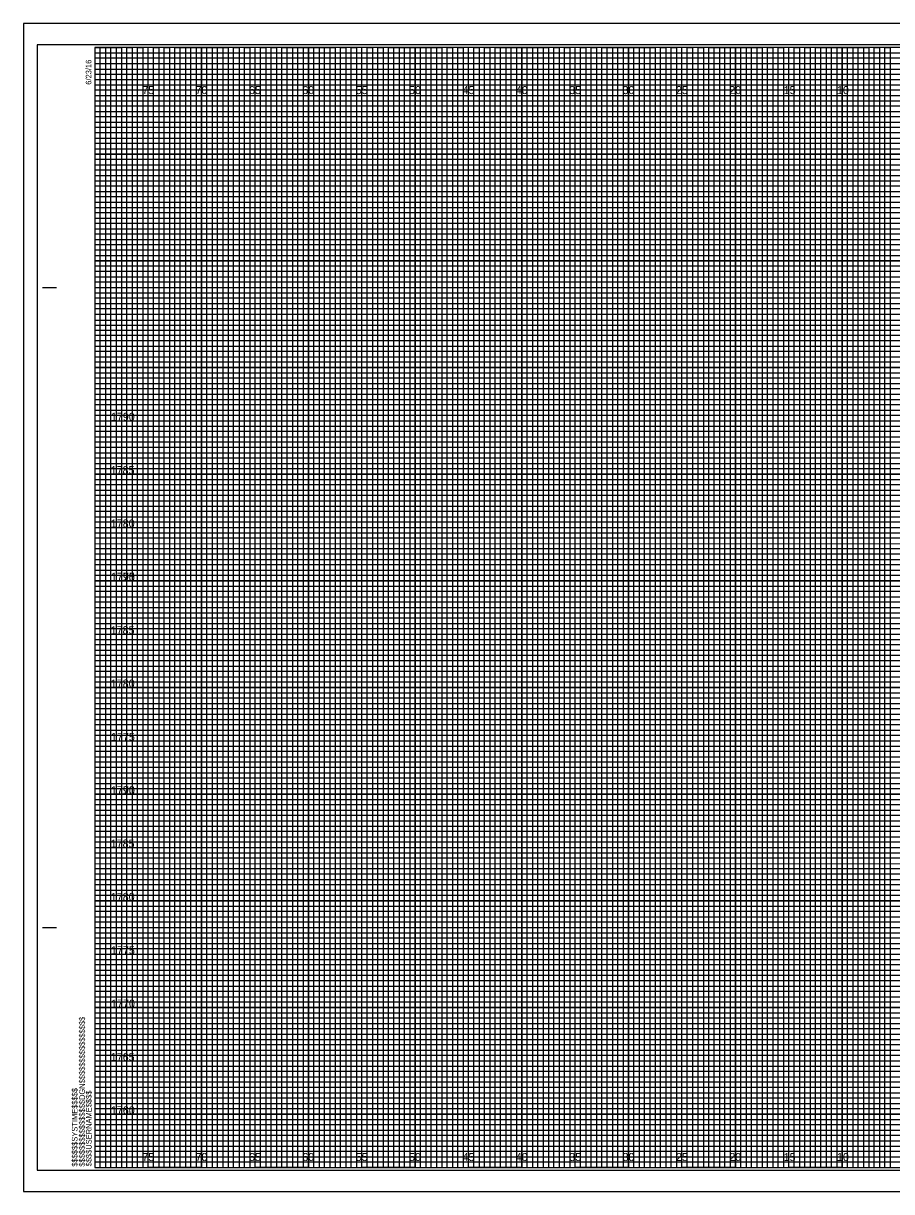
# Model space of a CAD drawing. Extents: x -7 to 162, y -2 to 217.
# Drawn here: x -6.7 to 74.6, y 107.7 to 217.2 of the extents above; entities that cross this region are included whole.
import ezdxf

# ---------------------------------------------------------------- set-up
doc = ezdxf.new("R2010")
doc.units = 0
for name, color, linetype in [('Raster_Level_0', 7, 'Continuous'), ('Scratch_Level_3', 7, 'Continuous'), ('Sheet Cross Section CELL', 7, 'Continuous'), ('Sheet Cross Section Grid Major CELL', 7, 'Continuous'), ('Sheet Cross Section Grid Middle CELL', 7, 'Continuous'), ('Sheet Cross Section Grid Minor 1 CELL', 7, 'Continuous'), ('Sheet Cross Section Grid Minor 2 CELL', 7, 'Continuous'), ('Sheet Cutting Line CELL', 7, 'Continuous'), ('Sheet DOT Grid CELL', 7, 'Continuous'), ('Sheet Plot Border Inside CELL', 7, 'Continuous'), ('Sheet Plot Border Outside CELL', 7, 'Continuous')]:
    doc.layers.add(name, color=color, linetype=linetype)

msp = doc.modelspace()

# ---------------------------------------------------------------- linework, layer by layer
at = {"layer": 'Sheet Cross Section CELL'}
for p, q in [((-4.9, 192.5), (-3.65, 192.5)), ((-4.85, 192.5), (-3.6, 192.5)), ((-4.9, 132.5), (-3.65, 132.5)), ((-4.85, 132.5), (-3.6, 132.5)), ((0, 110), (0, 110)), ((0, 110), (0, 110)), ((0, 110), (0, 110)), ((0, 110), (0, 110)), ((0, 110), (0, 110)), ((0, 110), (0, 110)), ((0, 110), (0, 110))]:
    msp.add_line(p, q, dxfattribs=at)
msp.add_lwpolyline([(160, 215), (0, 215), (0, 110), (160, 110)], close=True, dxfattribs=at)
at = {"layer": 'Sheet Cross Section Grid Major CELL'}
for p, q in [((5, 215), (0, 215)), ((5, 110), (5, 215)), ((15, 215), (10, 215)), ((10, 215), (10, 110)), ((15, 110), (15, 215)), ((25, 215), (20, 215)), ((20, 215), (20, 110)), ((25, 110), (25, 215)), ((35, 215), (30, 215)), ((30, 215), (30, 110)), ((35, 110), (35, 215)), ((45, 215), (40, 215)), ((40, 215), (40, 110)), ((45, 110), (45, 215)), ((55, 215), (50, 215)), ((50, 215), (50, 110)), ((55, 110), (55, 215)), ((65, 215), (60, 215)), ((60, 215), (60, 110)), ((65, 110), (65, 215)), ((75, 215), (70, 215)), ((70, 215), (70, 110)), ((10, 110), (5, 110)), ((20, 110), (15, 110)), ((30, 110), (25, 110)), ((40, 110), (35, 110)), ((50, 110), (45, 110)), ((60, 110), (55, 110)), ((70, 110), (65, 110))]:
    msp.add_line(p, q, dxfattribs=at)
for points in [[(0, 210), (160, 210), (160, 205), (0, 205)], [(0, 200), (160, 200), (160, 195), (0, 195)], [(0, 190), (160, 190), (160, 185), (0, 185)], [(0, 180), (160, 180), (160, 175), (0, 175)], [(0, 170), (160, 170), (160, 165), (0, 165)], [(0, 160), (160, 160), (160, 155), (0, 155)], [(0, 150), (160, 150), (160, 145), (0, 145)], [(0, 140), (160, 140), (160, 135), (0, 135)], [(0, 130), (160, 130), (160, 125), (0, 125)], [(0, 120), (160, 120), (160, 115), (0, 115)]]:
    msp.add_lwpolyline(points, dxfattribs=at)
at = {"layer": 'Sheet Cross Section Grid Middle CELL'}
for points in [[(0, 215), (2.5, 215), (2.5, 110), (7.5, 110), (7.5, 215), (12.5, 215), (12.5, 110), (17.5, 110), (17.5, 215), (22.5, 215), (22.5, 110), (27.5, 110), (27.5, 215), (32.5, 215), (32.5, 110), (37.5, 110), (37.5, 215), (42.5, 215), (42.5, 110), (47.5, 110), (47.5, 215), (52.5, 215), (52.5, 110), (57.5, 110), (57.5, 215), (62.5, 215), (62.5, 110), (67.5, 110), (67.5, 215), (72.5, 215), (72.5, 110), (77.5, 110)], [(0, 212.5), (137.5, 212.5)], [(0, 202.5), (160, 202.5), (160, 207.5), (0, 207.5)], [(0, 192.5), (160, 192.5), (160, 197.5), (0, 197.5)], [(0, 182.5), (160, 182.5), (160, 187.5), (0, 187.5)], [(0, 172.5), (160, 172.5), (160, 177.5), (0, 177.5)], [(0, 162.5), (160, 162.5), (160, 167.5), (0, 167.5)], [(0, 152.5), (160, 152.5), (160, 157.5), (0, 157.5)], [(0, 142.5), (160, 142.5), (160, 147.5), (0, 147.5)], [(0, 132.5), (160, 132.5), (160, 137.5), (0, 137.5)], [(0, 122.5), (160, 122.5), (160, 127.5), (0, 127.5)], [(0, 112.5), (160, 112.5), (160, 117.5), (0, 117.5)]]:
    msp.add_lwpolyline(points, dxfattribs=at)
at = {"layer": 'Sheet Cross Section Grid Minor 1 CELL'}
for p, q in [((0, 214.5), (130, 214.5)), ((130, 213.99), (0, 213.99)), ((0, 213.99), (0, 213.5)), ((0, 213.5), (130, 213.5)), ((130, 212.94), (0, 212.94)), ((0, 212.94), (0, 212)), ((0, 212), (160, 212))]:
    msp.add_line(p, q, dxfattribs=at)
for points in [[(0, 211.5), (135, 211.5), (160, 211.5), (160, 211), (0, 211)], [(0, 210.5), (160, 210.5), (160, 209.5), (0, 209.5)], [(0, 209), (160, 209), (160, 208.5), (0, 208.49)], [(0, 208), (160, 208), (160, 207), (0, 207)], [(0, 206.5), (160, 206.5), (160, 206), (0, 206)], [(0, 205.5), (160, 205.5), (160, 204.5), (0, 204.5)], [(0, 204), (160, 204), (160, 203.5), (0, 203.5)], [(0, 203), (160, 203), (160, 202), (0, 202)], [(0, 201.5), (160, 201.5), (160, 201), (0, 201)], [(0, 200.5), (160, 200.5), (160, 199.5), (0, 199.5)], [(0, 199), (160, 199), (160, 198.5), (0, 198.5)], [(0, 198), (160, 198), (160, 196.97), (160, 196.5), (160, 196), (0, 196)], [(0, 197), (160, 197), (160, 196.5), (0, 196.5)], [(0, 195.5), (160, 195.5), (160, 194.5), (0, 194.52)], [(0, 194.52), (160, 194.5), (160, 194), (0, 194)], [(0, 193.5), (160, 193.5), (160, 193), (0, 193)], [(0, 192), (160, 192), (160, 191.5), (0, 191.5)], [(0, 191), (160, 191), (160, 190.5), (0, 190.5)], [(-0.04, 189.44), (160, 189.44), (160, 188.94), (-0.04, 188.94)], [(0, 188.5), (160, 188.5), (160, 188), (0, 188)], [(0, 187), (160, 187), (160, 186.5), (0, 186.5)], [(0, 186), (160, 186), (160, 185.5), (0, 185.5)], [(0, 184.5), (160, 184.5), (160, 184), (0, 184)], [(0, 183.5), (160, 183.5), (160, 183), (0, 183)], [(0, 182), (160, 182), (160, 181.5), (0, 181.5)], [(0, 181), (160, 181), (160, 180.5), (0, 180.5)], [(0, 179.5), (160, 179.5), (160, 178.99), (0, 179)], [(0, 178.5), (160, 178.5), (160, 178), (0, 178)], [(0, 177), (160, 177), (160, 176.5), (0, 176.5)], [(0, 176), (160, 176), (160, 175.5), (0, 175.5)], [(0, 174.5), (160, 174.5), (160, 174), (0, 174)], [(0, 173.5), (160, 173.5), (160, 173), (0, 173)], [(0, 172), (160, 172), (160, 171.5), (0, 171.5)], [(0, 171), (160, 171), (160, 170.5), (0, 170.5)], [(0, 169.5), (160, 169.5), (160, 169), (0, 169)], [(0, 168.5), (160.03, 168.46), (160, 168), (0, 168)], [(0, 167), (160, 167), (160, 166.5), (0, 166.5)], [(0, 166), (160, 166), (160, 165.5), (0, 165.5)], [(0, 164.5), (160, 164.5), (160, 164), (0, 164)], [(0, 163.5), (160, 163.5), (160, 163), (0, 163)], [(0, 162), (160, 162), (160, 161.5), (0, 161.5)], [(0, 161), (160, 161), (160, 160.5), (0, 160.5)], [(0, 159.5), (160, 159.5), (160, 159), (0, 159)], [(0, 158.5), (160, 158.5), (160, 158), (0, 158)], [(0, 157), (160, 157), (160, 156.5), (0, 156.5)], [(0, 156), (160, 156), (160, 155.5), (0, 155.5)], [(0, 154.5), (160, 154.5), (160, 154), (0, 154)], [(0, 153.5), (160, 153.5), (160, 153), (0, 153)], [(0, 152), (160, 152), (160, 151.5), (0, 151.5)], [(0, 151), (160, 151), (160, 150.5), (0, 150.5)], [(0, 149.5), (160, 149.5), (160, 148.99), (0, 149)], [(0, 148.5), (160, 148.5), (160, 148), (0, 148)], [(0, 147), (160, 147), (160, 146.5), (0, 146.5)], [(0, 146), (160, 146), (160, 145.5), (0, 145.5)], [(0, 144.5), (160, 144.5), (160, 144), (0, 144)], [(0, 143.5), (160, 143.5), (160, 143), (0, 143)], [(0, 142), (160, 142), (160, 141.5), (0, 141.5)], [(0, 141), (160, 141), (160, 140.5), (0, 140.5)], [(0, 139.5), (160, 139.5), (160, 139), (0, 139)], [(0, 138.5), (160.03, 138.46), (160, 138), (0, 138)], [(0, 137), (160, 137), (160, 136.5), (0, 136.5)], [(0, 136), (160, 136), (160, 135.5), (0, 135.5)], [(0, 134.5), (160, 134.5), (160, 134), (0, 134)], [(0, 133.5), (160, 133.5), (160, 133), (0, 133)], [(0, 132), (160, 132), (160, 131.5), (0, 131.5)], [(0, 131), (160, 131), (160, 130.5), (0, 130.5)], [(0, 129.5), (160, 129.5), (160, 129), (0, 129)], [(0, 128.5), (160, 128.5), (160, 128), (0, 128)], [(0, 127), (160, 127), (160, 126.5), (0, 126.5)], [(0, 126), (160, 126), (160, 125.5), (0, 125.5)], [(0, 124.5), (160, 124.5), (160, 124), (0, 124)], [(0, 123.5), (160, 123.5), (160, 123), (0, 123)], [(0, 122), (160, 122), (160, 121.5), (0, 121.5)], [(0, 121), (160, 121), (160, 120.5), (0, 120.5)], [(0, 119.5), (160, 119.5), (160, 119), (0, 119)], [(0, 118.5), (160, 118.5), (160, 118), (0, 118)], [(0, 117), (160, 117), (160, 116.5), (0, 116.5)], [(0, 116), (160, 116), (160, 115.5), (0, 115.5)], [(0, 114.5), (160, 114.5), (160, 114), (0, 114)], [(0, 113.5), (160, 113.5), (160, 113), (0, 113)], [(0, 112), (160, 112), (160, 111.5), (0, 111.5)], [(0, 111), (160, 111), (160, 110.5), (0, 110.5)]]:
    msp.add_lwpolyline(points, dxfattribs=at)
at = {"layer": 'Sheet Cross Section Grid Minor 2 CELL'}
for points in [[(0, 110), (0.5, 110), (0.5, 215), (1, 215), (1, 110)], [(1, 110), (1.5, 110), (1.5, 215), (2, 215), (2, 110)], [(2.5, 110), (3, 110), (3, 215), (3.5, 215), (3.5, 110)], [(3.5, 110), (4, 110), (4, 215), (4.5, 215), (4.5, 110)], [(5, 110), (5.5, 110), (5.5, 215), (6, 215), (6, 110)], [(6, 110), (6.5, 110), (6.5, 215), (7, 215), (7, 110)], [(7.5, 110), (8, 110), (8, 215), (8.5, 215), (8.5, 110)], [(8.5, 110), (9, 110), (9, 215), (9.5, 215), (9.5, 110)], [(10, 110), (10.5, 110), (10.5, 215), (11, 215), (11, 110)], [(11, 110), (11.5, 110), (11.5, 215), (12, 215), (12, 110)], [(12.5, 110), (13, 110), (13, 215), (13.5, 215), (13.5, 110)], [(13.5, 110), (14, 110), (14, 215), (14.5, 215), (14.5, 110)], [(15, 110), (15.5, 110), (15.5, 215), (16, 215), (16, 110)], [(16, 110), (16.5, 110), (16.5, 215), (17, 215), (17, 110)], [(17.5, 110), (18, 110), (18, 215), (18.5, 215), (18.5, 110)], [(18.5, 110), (19, 110), (19, 215), (19.5, 215), (19.5, 110)], [(20, 110), (20.5, 110), (20.5, 215), (21, 215), (21, 110)], [(21, 110), (21.5, 110), (21.5, 215), (22, 215), (22, 110)], [(22.5, 110), (23, 110), (23, 215), (23.5, 215), (23.5, 110)], [(23.5, 110), (24, 110), (24, 215), (24.5, 215), (24.5, 110)], [(25, 110), (25.5, 110), (25.5, 215), (26, 215), (26, 110)], [(26, 110), (26.5, 110), (26.5, 215), (27, 215), (27, 110)], [(27.5, 110), (28, 110), (28, 215), (28.5, 215), (28.5, 110)], [(28.5, 110), (29, 110), (29, 215), (29.5, 215), (29.5, 110)], [(30, 110), (30.5, 110), (30.5, 215), (31, 215), (31, 110)], [(31, 110), (31.5, 110), (31.5, 215), (32, 215), (32, 110)], [(32.5, 110), (33, 110), (33, 215), (33.5, 215), (33.5, 110)], [(33.5, 110), (34, 110), (34, 215), (34.5, 215), (34.5, 110)], [(35, 110), (35.5, 110), (35.5, 215), (36, 215), (36, 110)], [(36, 110), (36.5, 110), (36.5, 215), (37, 215), (37, 110)], [(37.5, 110), (38, 110), (38, 215), (38.5, 215), (38.5, 110)], [(38.5, 110), (39, 110), (39, 215), (39.5, 215), (39.5, 110)], [(40, 110), (40.5, 110), (40.5, 215), (41, 215), (41, 110)], [(41, 110), (41.5, 110), (41.5, 215), (42, 215), (42, 110)], [(42.5, 110), (43, 110), (43, 215), (43.5, 215), (43.5, 110)], [(43.5, 110), (44, 110), (44, 215), (44.5, 215), (44.5, 110)], [(45, 110), (45.5, 110), (45.5, 215), (46, 215), (46, 110)], [(46, 110), (46.5, 110), (46.5, 215), (47, 215), (47, 110)], [(47.5, 110), (48, 110), (48, 215), (48.5, 215), (48.5, 110)], [(48.5, 110), (49, 110), (49, 215), (49.5, 215), (49.5, 110)], [(50, 110), (50.5, 110), (50.5, 215), (51, 215), (51, 110)], [(51, 110), (51.5, 110), (51.5, 215), (52, 215), (52, 110)], [(52.5, 110), (53, 110), (53, 215), (53.5, 215), (53.5, 110)], [(53.5, 110), (54, 110), (54, 215), (54.5, 215), (54.5, 110)], [(55, 110), (55.5, 110), (55.5, 215), (56, 215), (56, 110)], [(56, 110), (56.5, 110), (56.5, 215), (57, 215), (57, 110)], [(57.5, 110), (58, 110), (58, 215), (58.5, 215), (58.5, 110)], [(58.5, 110), (59, 110), (59, 215), (59.5, 215), (59.5, 110)], [(60, 110), (60.5, 110), (60.5, 215), (61, 215), (61, 110)], [(61, 110), (61.5, 110), (61.5, 215), (62, 215), (62, 110)], [(62.5, 110), (63, 110), (63, 215), (63.5, 215), (63.5, 110)], [(63.5, 110), (64, 110), (64, 215), (64.5, 215), (64.5, 110)], [(65, 110), (65.5, 110), (65.5, 215), (66, 215), (66, 110)], [(66, 110), (66.5, 110), (66.5, 215), (67, 215), (67, 110)], [(67.5, 110), (68, 110), (68, 215), (68.5, 215), (68.5, 110)], [(68.5, 110), (69, 110), (69, 215), (69.5, 215), (69.5, 110)], [(70, 110), (70.5, 110), (70.5, 215), (71, 215), (71, 110)], [(71, 110), (71.5, 110), (71.5, 215), (72, 215), (72, 110)], [(72.5, 110), (73, 110), (73, 215), (73.5, 215), (73.5, 110)], [(73.5, 110), (74, 110), (74, 215), (74.5, 215), (74.5, 110)]]:
    msp.add_lwpolyline(points, dxfattribs=at)
at = {"layer": 'Sheet Cutting Line CELL'}
for p, q in [((161.65, 217.25), (-6.7, 217.25)), ((-6.7, 217.25), (-6.7, 107.75)), ((-6.7, 107.75), (161.65, 107.75))]:
    msp.add_line(p, q, dxfattribs=at)
at = {"layer": 'Sheet DOT Grid CELL'}
for p, q in [((5, 110), (5, 215)), ((10, 110), (10, 215)), ((15, 110), (15, 215)), ((20, 110), (20, 215)), ((25, 110), (25, 215)), ((30, 110), (30, 215)), ((35, 110), (35, 215)), ((40, 110), (40, 215)), ((45, 110), (45, 215)), ((50, 110), (50, 215)), ((55, 110), (55, 215)), ((60, 110), (60, 215)), ((65, 110), (65, 215)), ((70, 110), (70, 215)), ((0, 210), (160, 210)), ((0, 205), (160, 205)), ((0, 200), (160, 200)), ((0, 195), (160, 195)), ((0, 190), (160, 190)), ((0, 185), (160, 185)), ((0, 180), (160, 180)), ((0, 175), (160, 175)), ((0, 170), (160, 170)), ((0, 165), (160, 165)), ((0, 160), (160, 160)), ((0, 155), (160, 155)), ((0, 150), (160, 150)), ((0, 145), (160, 145)), ((0, 140), (160, 140)), ((0, 135), (160, 135)), ((0, 130), (160, 130)), ((0, 125), (160, 125)), ((0, 120), (160, 120)), ((0, 115), (160, 115))]:
    msp.add_line(p, q, dxfattribs=at)
at = {"layer": 'Sheet Plot Border Inside CELL'}
msp.add_lwpolyline([(-5.4, 109.75), (161.2, 109.75), (161.2, 215.25), (-5.4, 215.25)], close=True, dxfattribs=at)
at = {"layer": 'Sheet Plot Border Outside CELL'}
msp.add_lwpolyline([(-6.7, 107.75), (161.65, 107.75), (161.65, 217.25), (-6.7, 217.25)], close=True, dxfattribs=at)

# ---------------------------------------------------------------- texts
at = {"layer": 'Raster_Level_0'}
for s, p in [('75', (4.44, 210.62)), ('70', (9.43, 210.62)), ('65', (14.44, 210.62)), ('60', (19.43, 210.62)), ('55', (24.44, 210.62)), ('50', (29.43, 210.62)), ('45', (34.44, 210.62)), ('40', (39.43, 210.62)), ('35', (44.44, 210.62)), ('30', (49.43, 210.62)), ('25', (54.44, 210.62)), ('20', (59.43, 210.62)), ('15', (64.53, 210.62)), ('10', (69.52, 210.62)), ('75', (4.44, 110.62)), ('70', (9.43, 110.62)), ('65', (14.44, 110.62)), ('60', (19.43, 110.62)), ('55', (24.44, 110.62)), ('50', (29.43, 110.62)), ('45', (34.44, 110.62)), ('40', (39.43, 110.62)), ('35', (44.44, 110.62)), ('30', (49.43, 110.62)), ('25', (54.44, 110.62)), ('20', (59.43, 110.62)), ('15', (64.53, 110.62)), ('10', (69.52, 110.62))]:
    msp.add_text(s, height=0.75, dxfattribs=at).set_placement(p)
at = {"layer": 'Scratch_Level_3'}
for s, p in [('1790', (1.5, 180)), ('1785', (1.48, 175)), ('1780', (1.49, 170)), ('1790', (1.5, 165)), ('1775', (1.51, 165)), ('1785', (1.48, 160)), ('1780', (1.49, 155)), ('1775', (1.51, 150)), ('1790', (1.5, 145)), ('1770', (1.52, 145)), ('1785', (1.48, 140)), ('1780', (1.49, 135)), ('1775', (1.51, 130)), ('1770', (1.52, 125)), ('1765', (1.49, 120)), ('1760', (1.5, 115))]:
    msp.add_text(s, height=0.75, dxfattribs=at).set_placement(p)
at = {"layer": 'Sheet Cross Section CELL'}
for s, p in [('6/23/16', (-0.33, 211.5)), ('$$$$$$$$$$$$$$$$DGN$$$$$$$$$$$$$$$$', (-0.94, 110.09)), ('$$$$$$SYSTIME$$$$$', (-1.63, 110.09)), ('$$$$USERNAME$$$$', (-0.31, 110.12))]:
    msp.add_text(s, height=0.525, rotation=90, dxfattribs=at).set_placement(p)

doc.saveas('drawing.dxf')
